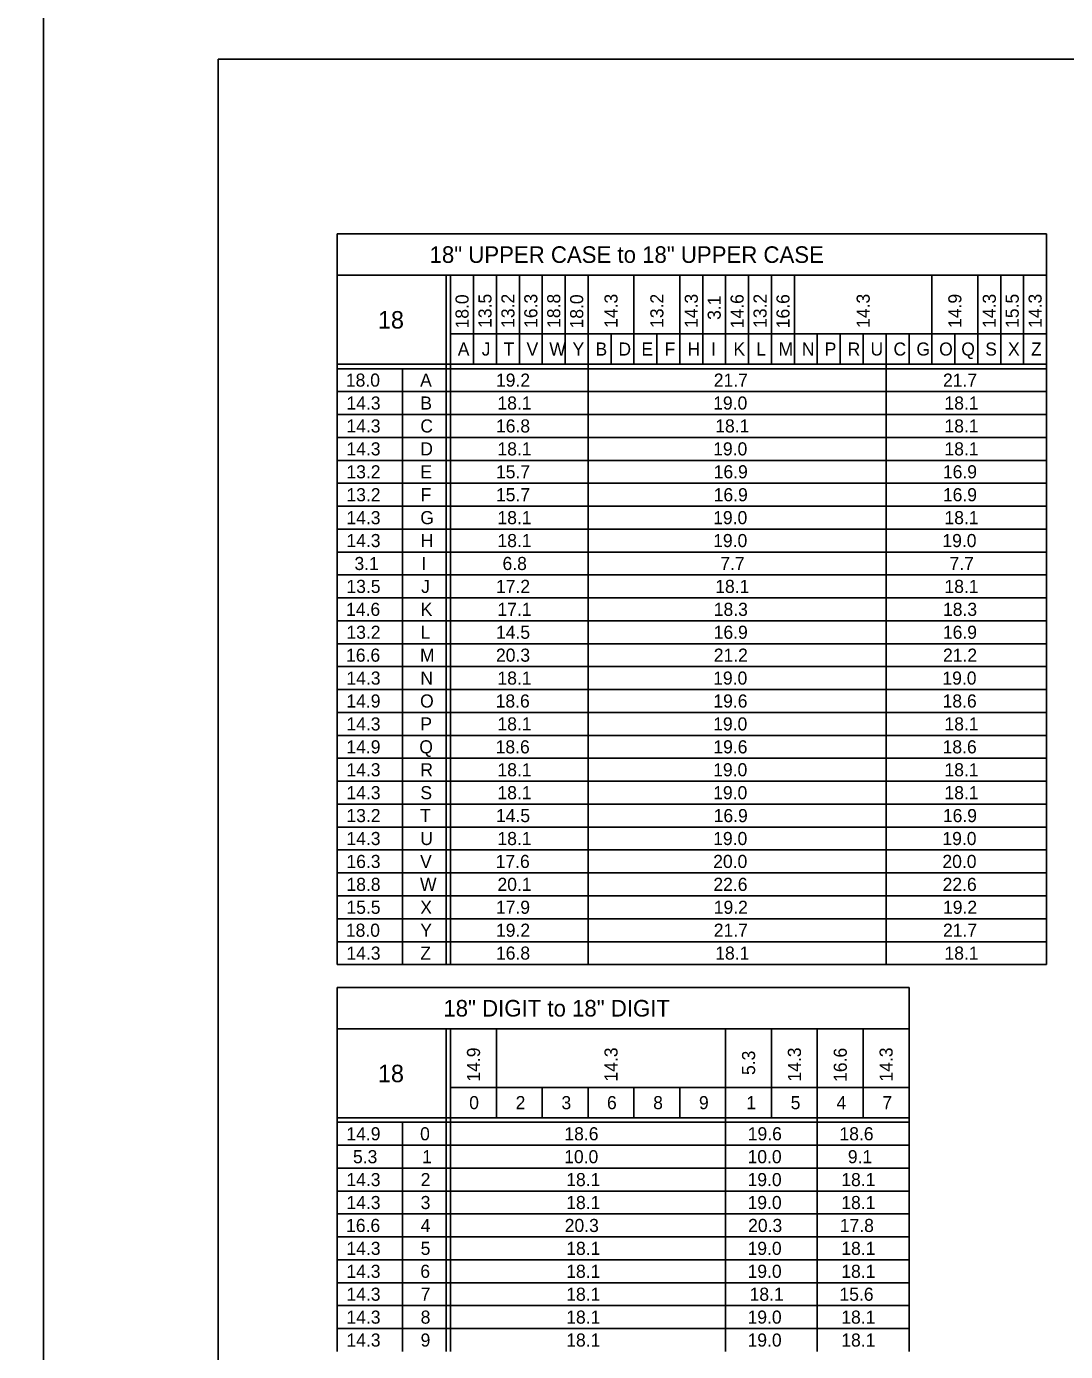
# Model space of a CAD drawing. Extents: x 637580 to 641849, y 297270 to 299646.
# Drawn here: x 640099.4 to 640337.3, y 298740.6 to 299044.1 of the extents above; entities that cross this region are included whole.
import ezdxf

# ---------------------------------------------------------------- set-up
doc = ezdxf.new("R2010")
doc.units = 0
for name, color, linetype in [('1', 7, 'Continuous'), ('2', 7, 'Continuous'), ('XCS-GRID-HVGL', 7, 'Continuous')]:
    doc.layers.add(name, color=color, linetype=linetype)

msp = doc.modelspace()

# ---------------------------------------------------------------- linework, layer by layer
at = {"layer": '1'}
for q in [(640929.31, 299036.63), (640143.31, 298472.63)]:
    msp.add_line((640143.31, 299036.63), q, dxfattribs=at)
at = {"layer": '2'}
for p, q in [((640333.01, 298996.63), (640170.51, 298996.63)), ((640170.51, 298996.63), (640170.51, 298829.25)), ((640333.01, 298996.63), (640333.01, 298829.25)), ((640170.51, 298987.13), (640333.01, 298987.13)), ((640195.51, 298987.13), (640195.51, 298829.25)), ((640196.51, 298987.13), (640196.51, 298829.25)), ((640201.76, 298987.13), (640201.76, 298966.75)), ((640207.01, 298987.13), (640207.01, 298966.75)), ((640212.26, 298987.13), (640212.26, 298966.75)), ((640217.51, 298987.13), (640217.51, 298966.75)), ((640222.76, 298987.13), (640222.76, 298966.75)), ((640228.01, 298987.13), (640228.01, 298829.25)), ((640238.51, 298987.13), (640238.51, 298966.75)), ((640249.01, 298987.13), (640249.01, 298966.75)), ((640254.26, 298987.13), (640254.26, 298966.75)), ((640259.51, 298987.13), (640259.51, 298966.75)), ((640264.76, 298987.13), (640264.76, 298966.75)), ((640270.01, 298987.13), (640270.01, 298966.75)), ((640275.26, 298987.13), (640275.26, 298966.75)), ((640306.76, 298987.13), (640306.76, 298966.75)), ((640317.26, 298987.13), (640317.26, 298966.75)), ((640322.51, 298987.13), (640322.51, 298966.75)), ((640327.76, 298987.13), (640327.76, 298966.75)), ((640196.51, 298973.75), (640333.01, 298973.75)), ((640233.26, 298973.75), (640233.26, 298966.75)), ((640243.76, 298973.75), (640243.76, 298966.75)), ((640280.51, 298973.75), (640280.51, 298966.75)), ((640285.76, 298973.75), (640285.76, 298966.75)), ((640291.01, 298973.75), (640291.01, 298966.75)), ((640291.01, 298973.75), (640291.01, 298966.75)), ((640296.26, 298973.75), (640296.26, 298829.25)), ((640301.51, 298973.75), (640301.51, 298966.75)), ((640312.01, 298973.75), (640312.01, 298966.75)), ((640333.01, 298966.75), (640170.51, 298966.75)), ((640333.01, 298965.75), (640170.51, 298965.75)), ((640185.51, 298965.75), (640185.51, 298829.25)), ((640333.01, 298960.5), (640170.51, 298960.5)), ((640333.01, 298955.25), (640170.51, 298955.25)), ((640333.01, 298950), (640170.51, 298950)), ((640333.01, 298944.75), (640170.51, 298944.75)), ((640333.01, 298939.5), (640170.51, 298939.5)), ((640333.01, 298934.25), (640170.51, 298934.25)), ((640333.01, 298929), (640170.51, 298929)), ((640333.01, 298923.75), (640170.51, 298923.75)), ((640333.01, 298918.5), (640170.51, 298918.5)), ((640333.01, 298913.25), (640170.51, 298913.25)), ((640333.01, 298908), (640170.51, 298908)), ((640333.01, 298902.75), (640170.51, 298902.75)), ((640333.01, 298897.5), (640170.51, 298897.5)), ((640333.01, 298892.25), (640170.51, 298892.25)), ((640333.01, 298887), (640170.51, 298887)), ((640333.01, 298881.75), (640170.51, 298881.75)), ((640333.01, 298876.5), (640170.51, 298876.5)), ((640333.01, 298871.25), (640170.51, 298871.25)), ((640333.01, 298866), (640170.51, 298866)), ((640333.01, 298860.75), (640170.51, 298860.75)), ((640333.01, 298855.5), (640170.51, 298855.5)), ((640333.01, 298850.25), (640170.51, 298850.25)), ((640333.01, 298845), (640170.51, 298845)), ((640333.01, 298839.75), (640170.51, 298839.75)), ((640333.01, 298834.5), (640170.51, 298834.5)), ((640170.51, 298829.25), (640170.51, 298829.25)), ((640170.51, 298829.25), (640333.01, 298829.25)), ((640301.51, 298824), (640170.51, 298824)), ((640170.51, 298824), (640170.51, 298740.63)), ((640301.51, 298740.63), (640301.51, 298824)), ((640170.51, 298814.5), (640301.51, 298814.5)), ((640195.51, 298814.5), (640195.51, 298740.63)), ((640196.51, 298814.5), (640196.51, 298740.63)), ((640207.01, 298814.5), (640207.01, 298794.13)), ((640259.51, 298814.5), (640259.51, 298740.63)), ((640270.01, 298814.5), (640270.01, 298794.13)), ((640280.51, 298814.5), (640280.51, 298740.63)), ((640291.01, 298814.5), (640291.01, 298794.13)), ((640196.51, 298801.13), (640301.51, 298801.13)), ((640217.51, 298801.13), (640217.51, 298794.13)), ((640228.01, 298801.13), (640228.01, 298794.13)), ((640238.51, 298801.13), (640238.51, 298794.13)), ((640249.01, 298801.13), (640249.01, 298794.13)), ((640301.51, 298794.13), (640170.51, 298794.13)), ((640301.51, 298793.13), (640170.51, 298793.13)), ((640185.51, 298793.13), (640185.51, 298740.63)), ((640301.51, 298787.88), (640170.51, 298787.88)), ((640301.51, 298782.63), (640170.51, 298782.63)), ((640301.51, 298777.38), (640170.51, 298777.38)), ((640301.51, 298772.13), (640170.51, 298772.13)), ((640301.51, 298766.88), (640170.51, 298766.88)), ((640301.51, 298761.63), (640170.51, 298761.63)), ((640301.51, 298756.38), (640170.51, 298756.38)), ((640301.51, 298751.13), (640170.51, 298751.13)), ((640301.51, 298745.88), (640170.51, 298745.88))]:
    msp.add_line(p, q, dxfattribs=at)
at = {"layer": 'XCS-GRID-HVGL'}
for points in [[(639262.31, 299051.63), (640103.31, 299051.63), (640103.31, 298457.63), (639262.31, 298457.63)], [(640103.31, 299051.63), (640944.31, 299051.63), (640944.31, 298457.63), (640103.31, 298457.63)]]:
    msp.add_lwpolyline(points, close=True, dxfattribs=at)

# ---------------------------------------------------------------- texts
at = {"layer": '2'}
for s, height, p in [('18" UPPER CASE to 18" UPPER CASE', 3.8, (640191.7, 298989.98)), ('18', 4, (640179.88, 298974.94)), ('A', 3, (640198.16, 298968.75)), ('J', 3, (640203.64, 298968.75)), ('T', 3, (640208.64, 298968.75)), ('V', 3, (640213.91, 298968.75)), ('W', 3, (640219.13, 298968.75)), ('Y', 3, (640224.44, 298968.75)), ('B', 3, (640229.7, 298968.75)), ('D', 3, (640234.95, 298968.75)), ('E', 3, (640240.22, 298968.75)), ('F', 3, (640245.52, 298968.75)), ('H', 3, (640250.79, 298968.75)), ('I', 3, (640256.2, 298968.75)), ('K', 3, (640261.29, 298968.75)), ('L', 3, (640266.54, 298968.75)), ('M', 3, (640271.63, 298968.75)), ('N', 3, (640276.95, 298968.75)), ('P', 3, (640282.2, 298968.75)), ('R', 3, (640287.45, 298968.75)), ('U', 3, (640292.69, 298968.75)), ('C', 3, (640297.95, 298968.75)), ('G', 3, (640303.2, 298968.75)), ('O', 3, (640308.41, 298968.75)), ('Q', 3, (640313.48, 298968.75)), ('S', 3, (640318.97, 298968.75)), ('X', 3, (640324.19, 298968.75)), ('Z', 3, (640329.45, 298968.75)), ('18.0', 3, (640172.53, 298961.63)), ('A', 3, (640189.53, 298961.63)), ('19.2', 3, (640206.91, 298961.63)), ('21.7', 3, (640256.79, 298961.63)), ('21.7', 3, (640309.29, 298961.63)), ('14.3', 3, (640172.66, 298956.38)), ('B', 3, (640189.58, 298956.38)), ('18.1', 3, (640207.25, 298956.38)), ('19.0', 3, (640256.66, 298956.38)), ('18.1', 3, (640309.63, 298956.38)), ('14.3', 3, (640172.66, 298951.13)), ('C', 3, (640189.58, 298951.13)), ('16.8', 3, (640206.91, 298951.13)), ('18.1', 3, (640257.13, 298951.13)), ('18.1', 3, (640309.63, 298951.13)), ('14.3', 3, (640172.66, 298945.88)), ('D', 3, (640189.58, 298945.88)), ('18.1', 3, (640207.25, 298945.88)), ('19.0', 3, (640256.66, 298945.88)), ('18.1', 3, (640309.63, 298945.88)), ('13.2', 3, (640172.66, 298940.63)), ('E', 3, (640189.59, 298940.63)), ('15.7', 3, (640206.91, 298940.63)), ('16.9', 3, (640256.77, 298940.63)), ('16.9', 3, (640309.27, 298940.63)), ('13.2', 3, (640172.66, 298935.38)), ('F', 3, (640189.65, 298935.38)), ('15.7', 3, (640206.91, 298935.38)), ('16.9', 3, (640256.77, 298935.38)), ('16.9', 3, (640309.27, 298935.38)), ('14.3', 3, (640172.66, 298930.13)), ('G', 3, (640189.58, 298930.13)), ('18.1', 3, (640207.25, 298930.13)), ('19.0', 3, (640256.66, 298930.13)), ('18.1', 3, (640309.63, 298930.13)), ('14.3', 3, (640172.66, 298924.88)), ('H', 3, (640189.66, 298924.88)), ('18.1', 3, (640207.25, 298924.88)), ('19.0', 3, (640256.66, 298924.88)), ('19.0', 3, (640309.16, 298924.88)), ('3.1', 3, (640174.5, 298919.63)), ('I', 3, (640189.83, 298919.63)), ('6.8', 3, (640208.41, 298919.63)), ('7.7', 3, (640258.29, 298919.63)), ('7.7', 3, (640310.79, 298919.63)), ('13.5', 3, (640172.66, 298914.38)), ('J', 3, (640189.77, 298914.38)), ('17.2', 3, (640206.91, 298914.38)), ('18.1', 3, (640257.13, 298914.38)), ('18.1', 3, (640309.63, 298914.38)), ('14.6', 3, (640172.58, 298909.13)), ('K', 3, (640189.66, 298909.13)), ('17.1', 3, (640207.25, 298909.13)), ('18.3', 3, (640256.79, 298909.13)), ('18.3', 3, (640309.29, 298909.13)), ('13.2', 3, (640172.66, 298903.88)), ('L', 3, (640189.66, 298903.88)), ('14.5', 3, (640206.91, 298903.88)), ('16.9', 3, (640256.77, 298903.88)), ('16.9', 3, (640309.27, 298903.88)), ('16.6', 3, (640172.58, 298898.63)), ('M', 3, (640189.51, 298898.63)), ('20.3', 3, (640206.91, 298898.63)), ('21.2', 3, (640256.79, 298898.63)), ('21.2', 3, (640309.29, 298898.63)), ('14.3', 3, (640172.66, 298893.38)), ('N', 3, (640189.58, 298893.38)), ('18.1', 3, (640207.25, 298893.38)), ('19.0', 3, (640256.66, 298893.38)), ('19.0', 3, (640309.16, 298893.38)), ('14.9', 3, (640172.65, 298888.13)), ('O', 3, (640189.53, 298888.13)), ('18.6', 3, (640206.83, 298888.13)), ('19.6', 3, (640256.7, 298888.13)), ('18.6', 3, (640309.2, 298888.13)), ('14.3', 3, (640172.66, 298882.88)), ('P', 3, (640189.58, 298882.88)), ('18.1', 3, (640207.25, 298882.88)), ('19.0', 3, (640256.66, 298882.88)), ('18.1', 3, (640309.63, 298882.88)), ('14.9', 3, (640172.65, 298877.63)), ('Q', 3, (640189.35, 298877.63)), ('18.6', 3, (640206.83, 298877.63)), ('19.6', 3, (640256.7, 298877.63)), ('18.6', 3, (640309.2, 298877.63)), ('14.3', 3, (640172.66, 298872.38)), ('R', 3, (640189.58, 298872.38)), ('18.1', 3, (640207.25, 298872.38)), ('19.0', 3, (640256.66, 298872.38)), ('18.1', 3, (640309.63, 298872.38)), ('14.3', 3, (640172.66, 298867.13)), ('S', 3, (640189.59, 298867.13)), ('18.1', 3, (640207.25, 298867.13)), ('19.0', 3, (640256.66, 298867.13)), ('18.1', 3, (640309.63, 298867.13)), ('13.2', 3, (640172.66, 298861.88)), ('T', 3, (640189.52, 298861.88)), ('14.5', 3, (640206.91, 298861.88)), ('16.9', 3, (640256.77, 298861.88)), ('16.9', 3, (640309.27, 298861.88)), ('14.3', 3, (640172.66, 298856.63)), ('U', 3, (640189.57, 298856.63)), ('18.1', 3, (640207.25, 298856.63)), ('19.0', 3, (640256.66, 298856.63)), ('19.0', 3, (640309.16, 298856.63)), ('16.3', 3, (640172.66, 298851.38)), ('V', 3, (640189.53, 298851.38)), ('17.6', 3, (640206.83, 298851.38)), ('20.0', 3, (640256.66, 298851.38)), ('20.0', 3, (640309.16, 298851.38)), ('18.8', 3, (640172.66, 298846.13)), ('W', 3, (640189.51, 298846.13)), ('20.1', 3, (640207.25, 298846.13)), ('22.6', 3, (640256.7, 298846.13)), ('22.6', 3, (640309.2, 298846.13)), ('15.5', 3, (640172.66, 298840.88)), ('X', 3, (640189.57, 298840.88)), ('17.9', 3, (640206.9, 298840.88)), ('19.2', 3, (640256.79, 298840.88)), ('19.2', 3, (640309.29, 298840.88)), ('18.0', 3, (640172.53, 298835.63)), ('Y', 3, (640189.57, 298835.63)), ('19.2', 3, (640206.91, 298835.63)), ('21.7', 3, (640256.79, 298835.63)), ('21.7', 3, (640309.29, 298835.63)), ('14.3', 3, (640172.66, 298830.38)), ('Z', 3, (640189.58, 298830.38)), ('16.8', 3, (640206.91, 298830.38)), ('18.1', 3, (640257.13, 298830.38)), ('18.1', 3, (640309.63, 298830.38)), ('18" DIGIT to 18" DIGIT', 3.8, (640194.86, 298817.35)), ('18', 4, (640179.88, 298802.31)), ('0', 3, (640200.78, 298796.13)), ('2', 3, (640211.41, 298796.13)), ('3', 3, (640221.91, 298796.13)), ('6', 3, (640232.33, 298796.13)), ('8', 3, (640242.91, 298796.13)), ('9', 3, (640253.4, 298796.13)), ('1', 3, (640264.25, 298796.13)), ('5', 3, (640274.41, 298796.13)), ('4', 3, (640284.91, 298796.13)), ('7', 3, (640295.41, 298796.13)), ('14.9', 3, (640172.65, 298789)), ('0', 3, (640189.53, 298789)), ('18.6', 3, (640222.58, 298789)), ('19.6', 3, (640264.58, 298789)), ('18.6', 3, (640285.58, 298789)), ('5.3', 3, (640174.16, 298783.75)), ('1', 3, (640190, 298783.75)), ('10.0', 3, (640222.53, 298783.75)), ('10.0', 3, (640264.53, 298783.75)), ('9.1', 3, (640287.5, 298783.75)), ('14.3', 3, (640172.66, 298778.5)), ('2', 3, (640189.66, 298778.5)), ('18.1', 3, (640223, 298778.5)), ('19.0', 3, (640264.53, 298778.5)), ('18.1', 3, (640286, 298778.5)), ('14.3', 3, (640172.66, 298773.25)), ('3', 3, (640189.66, 298773.25)), ('18.1', 3, (640223, 298773.25)), ('19.0', 3, (640264.53, 298773.25)), ('18.1', 3, (640286, 298773.25)), ('16.6', 3, (640172.58, 298768)), ('4', 3, (640189.66, 298768)), ('20.3', 3, (640222.66, 298768)), ('20.3', 3, (640264.66, 298768)), ('17.8', 3, (640285.66, 298768)), ('14.3', 3, (640172.66, 298762.75)), ('5', 3, (640189.66, 298762.75)), ('18.1', 3, (640223, 298762.75)), ('19.0', 3, (640264.53, 298762.75)), ('18.1', 3, (640286, 298762.75)), ('14.3', 3, (640172.66, 298757.5)), ('6', 3, (640189.58, 298757.5)), ('18.1', 3, (640223, 298757.5)), ('19.0', 3, (640264.53, 298757.5)), ('18.1', 3, (640286, 298757.5)), ('14.3', 3, (640172.66, 298752.25)), ('7', 3, (640189.66, 298752.25)), ('18.1', 3, (640223, 298752.25)), ('18.1', 3, (640265, 298752.25)), ('15.6', 3, (640285.58, 298752.25)), ('14.3', 3, (640172.66, 298747)), ('8', 3, (640189.66, 298747)), ('18.1', 3, (640223, 298747)), ('19.0', 3, (640264.53, 298747)), ('18.1', 3, (640286, 298747)), ('14.3', 3, (640172.66, 298741.75)), ('9', 3, (640189.65, 298741.75)), ('18.1', 3, (640223, 298741.75)), ('19.0', 3, (640264.53, 298741.75)), ('18.1', 3, (640286, 298741.75))]:
    msp.add_text(s, height=height, dxfattribs=at).set_placement(p)
for s, p in [('18.0', (640200.64, 298974.96)), ('13.5', (640205.89, 298975.09)), ('13.2', (640211.14, 298975.09)), ('16.3', (640216.39, 298975.09)), ('18.8', (640221.64, 298975.09)), ('18.0', (640226.89, 298974.96)), ('14.3', (640234.76, 298975.09)), ('13.2', (640245.26, 298975.09)), ('14.3', (640253.14, 298975.09)), ('3.1', (640258.39, 298976.93)), ('14.6', (640263.64, 298975.01)), ('13.2', (640268.89, 298975.09)), ('16.6', (640274.14, 298975.01)), ('14.3', (640292.51, 298975.09)), ('14.9', (640313.51, 298975.08)), ('14.3', (640321.39, 298975.09)), ('15.5', (640326.64, 298975.09)), ('14.3', (640331.89, 298975.09)), ('14.9', (640203.26, 298802.45)), ('14.3', (640234.76, 298802.46)), ('5.3', (640266.26, 298803.96)), ('14.3', (640276.76, 298802.46)), ('16.6', (640287.26, 298802.38)), ('14.3', (640297.76, 298802.46))]:
    msp.add_text(s, height=3, rotation=90, dxfattribs=at).set_placement(p)

doc.saveas('drawing.dxf')
